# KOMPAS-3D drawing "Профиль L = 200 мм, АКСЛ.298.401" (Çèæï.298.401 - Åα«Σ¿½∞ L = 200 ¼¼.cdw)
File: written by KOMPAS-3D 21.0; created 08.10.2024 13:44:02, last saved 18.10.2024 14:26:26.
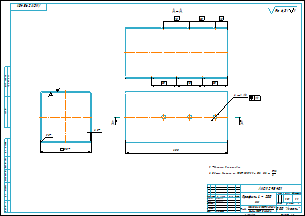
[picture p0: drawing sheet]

Sheet 1: A2, landscape

Document properties: Полное имя файла: C:\Users\Алексей Бочаров\YandexDisk\Соединения бруса\Соединения бруса\КВАТРО\АКСЛ.298.401 - Профиль L = 200 мм.cdw; Автор: Алексей Бочаров; Знак неуказанной шероховатости: 4; Параметр неуказанной шероховатости: Ra 6,3; Масса: 1.514806

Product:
- Part/product: Профиль L = 200 мм  | designation АКСЛ.298.401
    Масса: 1.210897
    Форматы листов документа: A2

Title block, sheet 1: Наименование: Профиль L = 200 / мм; designation: АКСЛ.298.401; Материал: Труба  100х100х2,5 ГОСТ 8639-82 Ст3сп ГОСТ 13663-86; Масса: 1,51; Количество листов документа: 1; organisation: ООО "Аксель"; Форматы листов документа: A2; stored path: C:\Users\Алексей Бочаров\Desktop\Соединения бруса\ТРИО\Профиль L = 300 мм (1) — копия.cdw; Разработал: Бочаров; Проверил: Захаров; Утвердил: Гелетей

Views: Вид 1, Спереди, Проекционный вид 2, Местный разрез 1, Проекционный вид 3
Referenced files in C:\Users\Алексей Бочаров\Desktop\Соединения бруса\КВАТРО\: Профиль L = 200 мм.m3d
Referenced files in C:\Users\Алексей Бочаров\YandexDisk\Соединения бруса\Соединения бруса\КВАТРО\: Профиль L = 200 мм.m3d
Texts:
  Ra 6,3
  Ra 6,3 ( )
  АКСЛ.298.400
  АКСЛ.298.401 Профиль L = 200 мм
Dimensions and other numbers on the sheet: 200; 6 отв.; 8; 25; 50; 100; 2,5; 2; 1:1; 1; 1,51

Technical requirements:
  *Размеры для справок.
  Общие допуски по ГОСТ 30893.1 - H12, h12,    IT12 2 .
